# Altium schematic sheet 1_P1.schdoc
size 218 x 157 mm; Symbol: Sheet-Symbol_A4; Device: Sheet-Symbol_A4; Company: 嘉立创EDA; Version: V1.0; Page Size: A4; @Project Name: FOC11; @Page Count: 1; @Update Date: 2025-03-01; @Create Date: 2025-02-02; @Schematic Name: Schematic4; @Page No: 1; @Page Name: P1; @Board Name: I2C编码器板; @Create Time: 10:34:26; @Update Time: 13:47:25; Width: 826; Height: 582; Region Start: 1; X Region Count: 6; Y Region Count: 4; Blade Width: 10; Title Block Position: 3
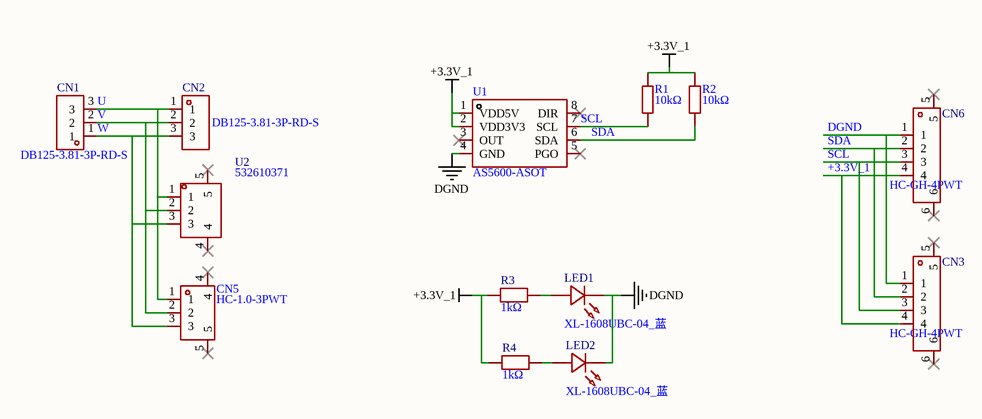
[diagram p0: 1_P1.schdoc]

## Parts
CN1  DB125-3.81-3P-RD-S  [CONN-TH_3P-P3.81_L7.4-W11.4]
CN2  DB125-3.81-3P-RD-S  [CONN-TH_3P-P3.81_L7.4-W11.4]
CN3  HC-GH-4PWT  [CONN-SMD_HC-GH-4PWT]
CN5  HC-1.0-3PWT  [CONN-SMD_3P-P1.0-HC-1.0-3PWT]
CN6  HC-GH-4PWT  [CONN-SMD_HC-GH-4PWT]
LED1  XL-1608UBC-04_蓝  [LED0603-RD_BLUE]
LED2  XL-1608UBC-04_蓝  [LED0603-RD_BLUE]
R1  10kΩ  [R0603]
R2  10kΩ  [R0603]
R3  1kΩ  [R0402]
R4  1kΩ  [R0402]
U1  AS5600-ASOT  [SOIC-8_L5.0-W4.0-P1.27-LS6.0-BL]
U2  532610371  [CONN-TH_532610371]

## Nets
+3.3V_1: CN3.4 CN6.4 R1.2 R2.2 R3.2 R4.2 U1.1(VDD5V) U1.2(VDD3V3)
DGND: CN3.1 CN6.1 LED1.1(K) LED2.1(K) U1.4(GND)
SCL: CN3.3 CN6.3 R1.1 U1.7(SCL)
SDA: CN3.2 CN6.2 R2.1 U1.6(SDA)
U: CN1.3 CN2.1 CN5.1 U2.1
V: CN1.2 CN2.2 CN5.2 U2.2
W: CN1.1 CN2.3 CN5.3 U2.3
NetLED1_2: LED1.2(A) R3.1
NetLED2_2: LED2.2(A) R4.1

Not connected (* = marked no-connect by the designer): CN3 5* 6*; CN5 4* 5*; CN6 5* 6*; U1 3(OUT)* 5(PGO)* 8(DIR)*; U2 4* 5*

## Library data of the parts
CN1 CN2 = DB125-3.81-3P-RD-S: Manufacturer: DIBO(地博电气); Add into BOM: yes; Pitch: 3.81mm; Number of PINs Per Row: 3; Current Rating (Max): 10A; Voltage Rating (Max): 300V; Wire Gauge - AWG: 16~26; Wire Gauge - mm2: 0.5~1
CN3 CN6 = HC-GH-4PWT_C2845399: Manufacturer: HCTL(华灿天禄); Add into BOM: yes; Pins Structure: 1x4P; Pitch: 1.25mm; Reference Series: GH; Number of PINs Per Row: 4; Current Rating (Max): 1A; Rated Voltage (Max): 50V; Plastic Material: LCP; Flame Retardant Rating: UL94V-0; Supplementary Features: 辅助焊脚; Z-Height of the Board: 4.25mm; X-Length of Bottom Edge on Board (Spacing Line): 8.25mm
CN5 = HC-1.0-3PWT: Manufacturer: HCTL(华灿天禄); Add into BOM: yes
LED1 LED2 = XL-1608UBC-04: Manufacturer: XINGLIGHT(成兴光); Add into BOM: yes; Emitted Color: 蓝色; Power Dissipation: 80mW; Forward Current: 25mA; Dominant Wavelength: 460nm~469nm; Peak Wavelength: 475nm; Lens Color: 无色透明透镜; Viewing Angle: 120°; Mounting Sytle: 正贴
R1 R2 = 0603WAF1002T5E: Manufacturer: UNI-ROYAL(厚声); Add into BOM: yes; Tolerance: ±1%; Power(Watts): 100mW; Overload Voltage (Max): 75V; Temperature Coefficient: ±100ppm/℃
R3 R4 = FRC0402J102 TS: Manufacturer: FOJAN(富捷); Add into BOM: yes; Tolerance: ±5%; Power(Watts): 62.5mW; Overload Voltage (Max): 50V; Temperature Coefficient: ±100ppm/℃
U1 = AS5600-ASOT: Manufacturer: ams(艾迈斯半导体); Add into BOM: yes
U2 = 532610371: Manufacturer: MOLEX; Add into BOM: yes; Pins Structure: 1x3P; Pitch: 1.25mm; Number of PINs Per Row: 3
